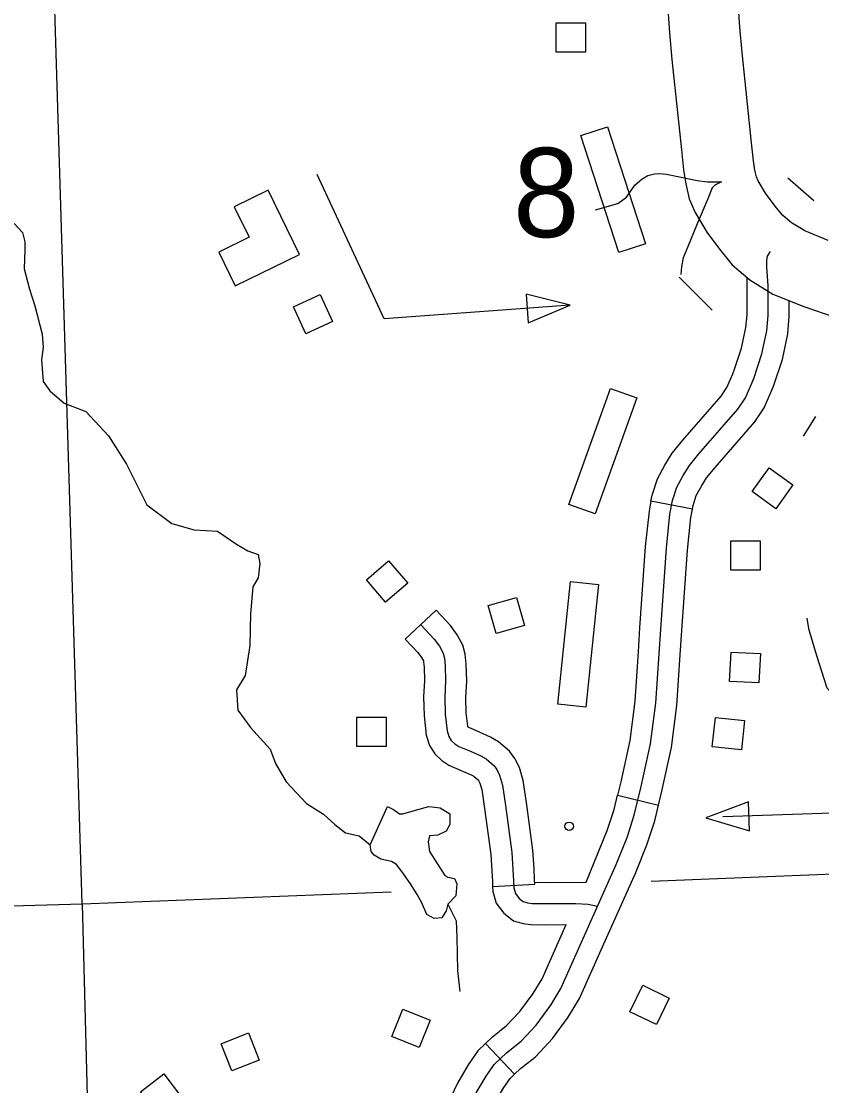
# Model space of a CAD drawing. Extents: x 155 to 3386, y 68 to 2138.
# Drawn here: x 1855.9 to 1937.1, y 1029.5 to 1137.5 of the extents above; entities that cross this region are included whole.
import ezdxf

# ---------------------------------------------------------------- set-up
doc = ezdxf.new("R2010")
doc.units = 0
for name, color, linetype in [('Level 10', 7, 'Continuous'), ('Level 31', 7, 'Continuous'), ('Level 32', 7, 'Continuous'), ('Level 35', 7, 'Continuous'), ('Level 5', 7, 'Continuous'), ('Level 56', 7, 'Continuous'), ('Level 57', 7, 'Continuous'), ('Level 58', 7, 'Continuous'), ('Level 6', 7, 'Continuous')]:
    doc.layers.add(name, color=color, linetype=linetype)

msp = doc.modelspace()

# ---------------------------------------------------------------- linework, layer by layer
at = {"layer": 'Level 10'}
for points in [[(1937.72, 1115.29), (1935.34, 1116.24), (1933.99, 1117.07), (1933.11, 1117.82), (1932.34, 1118.75), (1931.38, 1120.08), (1930.62, 1121.34), (1930.46, 1121.73), (1930.29, 1122.41), (1930.14, 1123.36), (1929.96, 1125.18), (1928.99, 1134.34), (1928.76, 1136.91), (1928.45, 1141.45)], [(1921.34, 1140.71), (1921.64, 1136.34), (1921.88, 1133.64), (1922.86, 1124.46), (1923.06, 1122.44), (1923.28, 1121.02), (1923.64, 1119.51), (1924.23, 1118.1), (1925.42, 1116.13), (1926.69, 1114.38), (1928, 1112.8), (1929.77, 1111.28), (1932.12, 1109.83), (1935.24, 1108.59), (1938.41, 1107.5)]]:
    msp.add_lwpolyline(points, dxfattribs=at)
at = {"layer": 'Level 31'}
for p, q in [((1923.95, 1088.02), (1919.74, 1088.82)), ((1923.95, 1088.02), (1919.74, 1088.82)), ((1923.95, 1088.02), (1923.95, 1088.02)), ((1923.95, 1088.02), (1923.95, 1088.02)), ((1897.95, 1077.76), (1894.83, 1074.83)), ((1897.95, 1077.76), (1894.83, 1074.83)), ((1897.95, 1077.76), (1897.95, 1077.76)), ((1916.35, 1059), (1920.51, 1057.99)), ((1916.35, 1059), (1920.51, 1057.99)), ((1903.68, 1049.73), (1907.96, 1049.98)), ((1903.68, 1049.73), (1907.96, 1049.98)), ((1903.68, 1049.73), (1903.68, 1049.73)), ((1905.92, 1030.71), (1902.97, 1033.82)), ((1905.92, 1030.71), (1902.97, 1033.82)), ((1905.92, 1030.71), (1905.92, 1030.71)), ((1905.92, 1030.71), (1905.92, 1030.71))]:
    msp.add_line(p, q, dxfattribs=at)
for points in [[(1902.02, 1028.81), (1903.02, 1030.51), (1903.83, 1031.68), (1905.1, 1032.88), (1906.57, 1034.06), (1908.1, 1035.69), (1909.58, 1037.7), (1910.61, 1039.39), (1916.23, 1051.99), (1917.33, 1054.71), (1918.06, 1056.99), (1918.77, 1059.89), (1919.7, 1064.21), (1920.24, 1068.33), (1920.74, 1075.86), (1921.31, 1084.05), (1921.67, 1087.51), (1921.94, 1088.91), (1922.38, 1090.25), (1923.01, 1091.42), (1923.65, 1092.46), (1924.62, 1093.63), (1928.57, 1098.17), (1929.33, 1099.33), (1930.17, 1101.27), (1931.01, 1103.78), (1931.51, 1106.12), (1931.64, 1107.66), (1931.64, 1110.7), (1931.51, 1112.57), (1931.51, 1113.24), (1931.57, 1113.68), (1931.88, 1114.17)], [(1928.04, 1101.74), (1928.17, 1102.03), (1928.93, 1104.34), (1929.38, 1106.44), (1929.5, 1107.75), (1929.5, 1111.51)], [(1931.98, 1100.04), (1932.17, 1100.51), (1933.08, 1103.21), (1933.63, 1105.8), (1933.78, 1107.56), (1933.78, 1109.17)], [(1919.74, 1088.82), (1919.86, 1089.44), (1920.4, 1091.1), (1921.15, 1092.49), (1921.9, 1093.71), (1922.99, 1095.01), (1926.86, 1099.47), (1927.44, 1100.36), (1928.04, 1101.74)], [(1923.95, 1088.02), (1924.02, 1088.38), (1924.35, 1089.4), (1924.87, 1090.35), (1925.39, 1091.2), (1926.25, 1092.24), (1930.27, 1096.87), (1931.23, 1098.31), (1931.98, 1100.04)], [(1919.74, 1088.82), (1919.55, 1087.82), (1919.17, 1084.24), (1918.6, 1076), (1918.44, 1073.54)], [(1919.74, 1088.82), (1919.55, 1087.82), (1919.17, 1084.24), (1918.6, 1076), (1918.44, 1073.54)], [(1922.71, 1073.25), (1922.88, 1075.71), (1923.44, 1083.86), (1923.8, 1087.19), (1923.95, 1088.02)], [(1922.71, 1073.25), (1922.88, 1075.71), (1923.44, 1083.86), (1923.8, 1087.19), (1923.95, 1088.02)], [(1902.43, 1065.36), (1902.28, 1065.42), (1901.28, 1065.86), (1901.2, 1065.91), (1901.17, 1066), (1901.02, 1067.36), (1900.98, 1068.92), (1901.07, 1070.6), (1901.02, 1072.29), (1900.91, 1073.3), (1900.68, 1074.22), (1900.1, 1075.28), (1899.41, 1076.22), (1897.95, 1077.76)], [(1902.43, 1065.36), (1902.28, 1065.42), (1901.28, 1065.86), (1901.2, 1065.91), (1901.17, 1066), (1901.02, 1067.36), (1900.98, 1068.92), (1901.07, 1070.6), (1901.02, 1072.29), (1900.91, 1073.3), (1900.68, 1074.22), (1900.1, 1075.28), (1899.41, 1076.22), (1897.95, 1077.76)], [(1896.39, 1076.29), (1897.76, 1074.84), (1898.29, 1074.13), (1898.67, 1073.43), (1898.8, 1072.92), (1898.88, 1072.14), (1898.92, 1070.63), (1898.84, 1068.94), (1898.88, 1067.22), (1899.07, 1065.55), (1899.26, 1064.95), (1899.49, 1064.57), (1899.87, 1064.22), (1900.27, 1063.96), (1901.43, 1063.46), (1902.5, 1062.99), (1903.03, 1062.68), (1903.83, 1062), (1904.1, 1061.62), (1904.4, 1061.03), (1904.69, 1060.04), (1905.01, 1057.96), (1905.63, 1053.21), (1905.75, 1051.46), (1905.8, 1050.32), (1905.84, 1049.61), (1906.01, 1049.04), (1906.39, 1048.53), (1906.79, 1048.22), (1907.23, 1048.09), (1907.69, 1048.03), (1909.06, 1048.01), (1912.13, 1048.03), (1913.38, 1047.96), (1914.34, 1047.76)], [(1894.83, 1074.83), (1896.11, 1073.47), (1896.48, 1072.97), (1896.66, 1072.64), (1896.68, 1072.55), (1896.74, 1072), (1896.78, 1070.65), (1896.69, 1068.97), (1896.74, 1067.07), (1896.96, 1065.1), (1897.29, 1064.06), (1897.81, 1063.21), (1898.55, 1062.52), (1899.26, 1062.06), (1900.57, 1061.49), (1900.73, 1061.42)], [(1894.83, 1074.83), (1896.11, 1073.47), (1896.48, 1072.97), (1896.66, 1072.64), (1896.68, 1072.55), (1896.74, 1072), (1896.78, 1070.65), (1896.69, 1068.97), (1896.74, 1067.07), (1896.96, 1065.1), (1897.29, 1064.06), (1897.81, 1063.21), (1898.55, 1062.52), (1899.26, 1062.06), (1900.57, 1061.49), (1900.73, 1061.42)], [(1918.44, 1073.54), (1918.1, 1068.54), (1917.59, 1064.57), (1916.68, 1060.37), (1916.35, 1059)], [(1918.44, 1073.54), (1918.1, 1068.54), (1917.59, 1064.57), (1916.68, 1060.37), (1916.35, 1059)], [(1920.51, 1057.99), (1920.85, 1059.42), (1921.82, 1063.84), (1922.37, 1068.12), (1922.71, 1073.25)], [(1920.51, 1057.99), (1920.85, 1059.42), (1921.82, 1063.84), (1922.37, 1068.12), (1922.71, 1073.25)], [(1907.96, 1049.98), (1907.94, 1050.43), (1907.89, 1051.58), (1907.76, 1053.43), (1907.13, 1058.26), (1906.79, 1060.51), (1906.4, 1061.83), (1905.94, 1062.74), (1905.41, 1063.47), (1904.28, 1064.43), (1903.48, 1064.9), (1902.43, 1065.36)], [(1907.96, 1049.98), (1907.94, 1050.43), (1907.89, 1051.58), (1907.76, 1053.43), (1907.13, 1058.26), (1906.79, 1060.51), (1906.4, 1061.83), (1905.94, 1062.74), (1905.41, 1063.47), (1904.28, 1064.43), (1903.48, 1064.9), (1902.43, 1065.36)], [(1900.73, 1061.42), (1901.52, 1061.08), (1901.78, 1060.93), (1902.24, 1060.53), (1902.26, 1060.51), (1902.4, 1060.24), (1902.59, 1059.58), (1902.88, 1057.66), (1903.49, 1052.99), (1903.61, 1051.35), (1903.66, 1050.22), (1903.68, 1049.73)], [(1900.73, 1061.42), (1901.52, 1061.08), (1901.78, 1060.93), (1902.24, 1060.53), (1902.26, 1060.51), (1902.4, 1060.24), (1902.59, 1059.58), (1902.88, 1057.66), (1903.49, 1052.99), (1903.61, 1051.35), (1903.66, 1050.22), (1903.68, 1049.73)], [(1913.18, 1050.18), (1915.31, 1055.44), (1916, 1057.57), (1916.35, 1059)], [(1914.84, 1043.62), (1918.2, 1051.15), (1919.34, 1053.98), (1920.13, 1056.4), (1920.51, 1057.99)], [(1903.68, 1049.73), (1903.71, 1049.24), (1904.06, 1048.06), (1904.84, 1047.03), (1905.79, 1046.27), (1906.79, 1045.99), (1907.53, 1045.89), (1909.05, 1045.86), (1911.16, 1045.88)], [(1907.95, 1050.17), (1909.07, 1050.15), (1913.18, 1050.18)], [(1902.97, 1033.82), (1903.69, 1034.5), (1905.11, 1035.64), (1906.45, 1037.07), (1907.8, 1038.9), (1908.71, 1040.39), (1911.16, 1045.88)], [(1905.92, 1030.71), (1906.5, 1031.27), (1908.02, 1032.48), (1909.76, 1034.32), (1911.35, 1036.5), (1912.51, 1038.38), (1914.84, 1043.62)], [(1902.97, 1033.82), (1902.19, 1033.08), (1901.21, 1031.66), (1900.12, 1029.81), (1899.44, 1028.36), (1899, 1026.8), (1898.88, 1025.02), (1898.84, 1023.53), (1898.93, 1018.11)], [(1902.97, 1033.82), (1902.19, 1033.08), (1901.21, 1031.66), (1900.12, 1029.81), (1899.44, 1028.36), (1899, 1026.8), (1898.88, 1025.02), (1898.84, 1023.53), (1898.93, 1018.11)], [(1903.22, 1018.18), (1903.13, 1023.51), (1903.16, 1024.83), (1903.24, 1026.06), (1903.47, 1026.84), (1903.92, 1027.8), (1904.83, 1029.36), (1905.47, 1030.28), (1905.92, 1030.71)], [(1903.22, 1018.18), (1903.13, 1023.51), (1903.16, 1024.83), (1903.24, 1026.06), (1903.47, 1026.84), (1903.92, 1027.8), (1904.83, 1029.36), (1905.47, 1030.28), (1905.92, 1030.71)]]:
    msp.add_lwpolyline(points, dxfattribs=at)
at = {"layer": 'Level 32'}
msp.add_lwpolyline([(1914.11, 1118.37), (1916.4, 1119.03), (1917.27, 1119.67), (1918.12, 1120.87), (1918.87, 1121.54), (1919.44, 1121.87), (1920.1, 1122.05), (1920.65, 1122.08), (1921.34, 1121.99), (1922.82, 1121.69), (1924.45, 1121.36), (1925.47, 1121.24), (1926.91, 1121.21), (1926.22, 1120.9), (1925.95, 1120.6), (1925.53, 1119.49), (1924.42, 1116.98), (1923.45, 1114.57), (1923, 1113.51), (1922.85, 1112.64), (1922.79, 1111.83)], dxfattribs=at)
at = {"layer": 'Level 35'}
for points in [[(1855.14, 1117.01), (1855.99, 1116.1), (1856.23, 1115.13), (1856.23, 1114.34), (1856.17, 1112.4), (1856.72, 1110.33), (1857.26, 1108.63), (1857.99, 1105.78), (1858.11, 1104.44), (1857.93, 1103.16), (1858.11, 1100.98), (1858.78, 1100.01), (1860.24, 1098.79), (1862.42, 1097.94), (1864.73, 1095.45), (1866.55, 1092.6), (1868.61, 1088.47), (1871.16, 1086.58), (1873.41, 1085.92), (1875.78, 1085.79), (1877.72, 1084.46), (1878.87, 1083.79), (1879.9, 1083.43), (1880.09, 1082.51), (1879.9, 1081.06), (1879.36, 1080.15), (1879.12, 1077.41), (1879.05, 1074.19), (1878.57, 1071.16), (1877.72, 1069.7), (1877.84, 1067.63), (1879.12, 1065.87), (1881.12, 1063.69), (1881.67, 1062.23), (1882.76, 1060.35), (1884.82, 1058.16), (1886.52, 1057.07), (1887.67, 1056.03), (1888.77, 1055.18), (1890.16, 1054.88), (1891.26, 1053.97)], [(1935.55, 1076.95), (1935.73, 1075.91), (1936.55, 1073.17), (1937.59, 1069.9), (1938.44, 1068.98), (1945.65, 1061.45), (1950.32, 1053.59), (1952.68, 1048.42), (1953.53, 1045.61), (1956.94, 1042.35), (1960.2, 1039.97), (1962.28, 1039.01), (1965.69, 1035.51), (1968.06, 1033.06), (1971.18, 1032.24), (1973.48, 1030.46), (1975.03, 1028.31)], [(1891.26, 1053.97), (1893.02, 1057.86)], [(1893.02, 1057.86), (1893.62, 1057.55), (1894.23, 1057.13), (1894.59, 1057.13), (1895.87, 1057.49), (1897.21, 1057.86), (1898.36, 1057.74), (1899.33, 1057.13), (1899.33, 1056.03), (1898.97, 1055.37), (1898.12, 1054.94), (1897.27, 1054.88), (1897.14, 1054.27), (1897.27, 1053.3), (1898.84, 1050.87), (1899.15, 1050.69), (1899.82, 1050.57), (1900.06, 1050.02), (1899.94, 1048.81), (1899.15, 1047.96), (1898.97, 1047.29), (1898.54, 1046.56), (1897.75, 1046.5), (1897.02, 1046.92), (1896.48, 1048.14), (1896.05, 1048.93), (1895.44, 1049.9), (1894.59, 1051.12), (1893.93, 1051.97), (1893.44, 1052.27), (1892.35, 1052.51), (1891.68, 1052.94), (1891.38, 1053.3), (1891.26, 1053.97)], [(1899.15, 1047.96), (1900, 1046.26), (1900.06, 1044.62), (1900.12, 1041.24), (1900.36, 1039.11)]]:
    msp.add_lwpolyline(points, dxfattribs=at)
at = {"layer": 'Level 5'}
for points in [[(1919.78, 1050.28), (1981.21, 1052.74)], [(1862.06, 1047.97), (1893.41, 1049.22)], [(1862.06, 1047.97), (1863.2, 1003.81)]]:
    msp.add_lwpolyline(points, dxfattribs=at)
at = {"layer": 'Level 56'}
for points in [[(1910.13, 1134.39), (1910.13, 1137.37), (1913.12, 1137.37), (1913.12, 1134.39)], [(1919.21, 1114.92), (1916.49, 1114.04), (1912.63, 1125.93), (1915.35, 1126.81)], [(1887.44, 1107.07), (1884.74, 1105.82), (1883.48, 1108.53), (1886.18, 1109.78)], [(1907.08, 1109.83), (1907.29, 1106.92), (1911.55, 1108.7)], [(1915.63, 1100.27), (1918.32, 1099.3), (1914.1, 1087.54), (1911.41, 1088.5)], [(1932.41, 1088.06), (1930, 1089.81), (1931.74, 1092.22), (1934.15, 1090.48)], [(1927.85, 1081.83), (1927.85, 1084.8), (1930.83, 1084.8), (1930.83, 1081.83)], [(1895.07, 1080.51), (1892.82, 1078.58), (1890.88, 1080.84), (1893.13, 1082.78)], [(1913.13, 1067.94), (1910.29, 1068.23), (1911.58, 1080.67), (1914.42, 1080.37)], [(1906.12, 1079.07), (1906.92, 1076.21), (1904.05, 1075.4), (1903.25, 1078.26)], [(1927.72, 1070.55), (1927.87, 1073.52), (1930.85, 1073.37), (1930.69, 1070.4)], [(1889.92, 1063.94), (1889.92, 1066.91), (1892.9, 1066.91), (1892.9, 1063.94)], [(1925.97, 1063.92), (1926.29, 1066.88), (1929.25, 1066.57), (1928.94, 1063.61)], [(1929.73, 1055.4), (1929.64, 1058.32), (1925.31, 1056.72)], [(1917.62, 1037.04), (1918.92, 1039.72), (1921.6, 1038.41), (1920.3, 1035.74)], [(1893.47, 1034.53), (1894.57, 1037.3), (1897.34, 1036.19), (1896.24, 1033.43)], [(1878.91, 1034.9), (1880.01, 1032.14), (1877.24, 1031.03), (1876.14, 1033.79)], [(1869.77, 1026.57), (1867.96, 1028.92), (1870.33, 1030.74), (1872.14, 1028.38)]]:
    msp.add_lwpolyline(points, close=True, dxfattribs=at)
for points in [[(1911.55, 1108.7), (1892.7, 1107.32), (1885.89, 1121.96)], [(1936.28, 1119.31), (1933.64, 1121.61)], [(1935.22, 1095.43), (1936.46, 1097.41)], [(1927.05, 1056.84), (1942.15, 1057.34)]]:
    msp.add_lwpolyline(points, dxfattribs=at)
msp.add_circle((1911.45, 1055.85), 0.429, dxfattribs=at)
at = {"layer": 'Level 57'}
msp.add_lwpolyline([(1925.95, 1108.2), (1922.6, 1111.56)], dxfattribs=at)
at = {"layer": 'Level 58'}
msp.add_lwpolyline([(1884.1, 1113.86), (1880.91, 1120.38), (1877.47, 1118.69), (1878.98, 1115.61), (1875.9, 1114.1), (1877.58, 1110.67)], close=True, dxfattribs=at)
at = {"layer": 'Level 6'}
msp.add_lwpolyline([(1807.32, 1046.44), (1862.06, 1047.97), (1857.33, 1202.89), (1933.53, 1204.84), (1931.34, 1271.07)], dxfattribs=at)

# ---------------------------------------------------------------- texts
at = {"layer": 'Level 56'}
msp.add_text('8', height=9.05, dxfattribs=at).set_placement((1905.76, 1115.62))

doc.saveas('drawing.dxf')
